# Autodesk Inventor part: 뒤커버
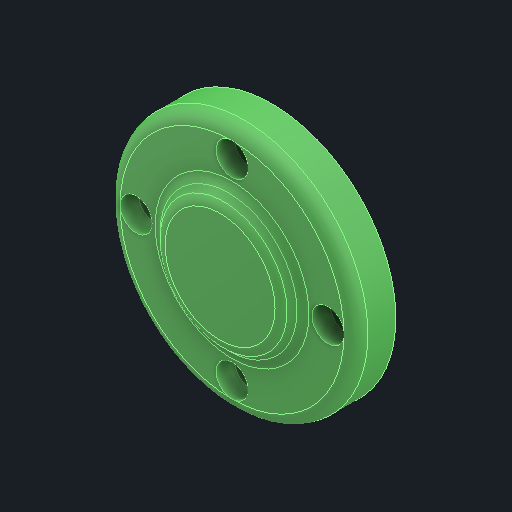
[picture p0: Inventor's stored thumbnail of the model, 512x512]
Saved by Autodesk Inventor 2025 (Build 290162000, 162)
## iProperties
Created: 2025-08
Part Number: 뒤커버
Material: 알루미늄 6061
Document SubType Name: Modeling
Designer: infra14
Density: 2.71 g/cm^3
Appearance: 기본값
Author: jhkim
Sending System: Autodesk Inventor 2026
Preprocessor: ST-DEVELOPER v20.1
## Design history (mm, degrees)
feature "솔리드1"
node "솔리드2"
